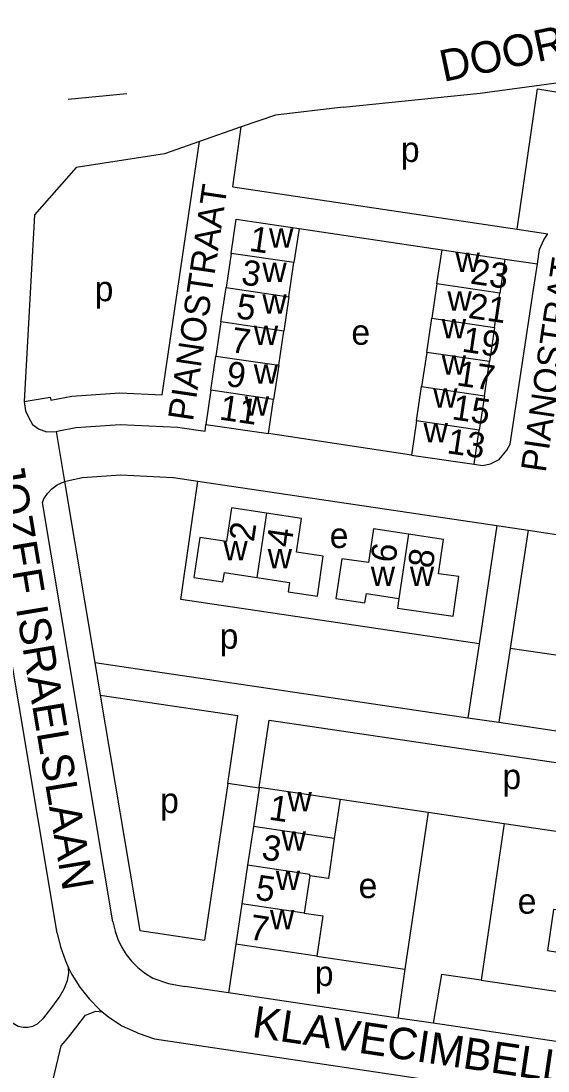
# Model space of a CAD drawing. Extents: x 163012 to 165277, y 382513 to 383987.
# Drawn here: x 164286.1 to 164369.8, y 383209.4 to 383376 of the extents above; entities that cross this region are included whole.
import ezdxf

# ---------------------------------------------------------------- set-up
doc = ezdxf.new("R2010")
doc.units = 0
for name, color, linetype in [('BLT_Basislijn', 7, 'Continuous'), ('BLT_Bebouwing', 7, 'Continuous'), ('BLT_Centroide', 7, 'Continuous'), ('BLT_Huisnummer', 7, 'Continuous'), ('BLT_Huisnummer_ tussenligend', 7, 'Continuous'), ('BLT_Onderverdeling_panden', 7, 'Continuous'), ('BLT_Straatnaam', 7, 'Continuous'), ('BLT_Straatnaam_verkleind', 7, 'Continuous'), ('BLT_Vlakafsluiter', 7, 'Continuous')]:
    doc.layers.add(name, color=color, linetype=linetype)

msp = doc.modelspace()

# ---------------------------------------------------------------- linework, layer by layer
at = {"layer": 'BLT_Basislijn'}
for p, q in [((164293.6, 383363.66), (164302.9, 383364.52)), ((164308.49, 383316.69), (164314.42, 383356.92)), ((164330.23, 383343.11), (164352.93, 383339.75)), ((164364.88, 383343.03), (164369.75, 383342.26)), ((164362.89, 383338.26), (164368.07, 383337.49)), ((164348.07, 383307.16), (164325.39, 383310.55)), ((164310.28, 383303.58), (164314.17, 383303)), ((164314.17, 383303), (164361.65, 383295.96)), ((164361.65, 383295.96), (164358.8, 383277.21)), ((164361.65, 383295.96), (164366.6, 383295.22)), ((164366.6, 383295.22), (164363.74, 383276.47)), ((164366.6, 383295.22), (164417.23, 383287.72)), ((164358.8, 383277.21), (164357.01, 383265.47)), ((164363.74, 383276.47), (164361.96, 383264.74)), ((164412.77, 383269.34), (164363.74, 383276.47)), ((164297.82, 383274.22), (164357.01, 383265.47)), ((164298.69, 383269.03), (164320.53, 383265.81)), ((164318.94, 383255.03), (164320.53, 383265.81)), ((164323.91, 383254.47), (164325.48, 383265.08)), ((164325.48, 383265.08), (164404.1, 383253.46)), ((164357.01, 383265.47), (164361.96, 383264.74)), ((164361.96, 383264.74), (164408.23, 383257.91)), ((164336.74, 383252.56), (164350.72, 383250.49)), ((164350.72, 383250.49), (164347.05, 383225.58)), ((164350.72, 383250.49), (164362.81, 383248.7)), ((164362.81, 383248.7), (164372.46, 383247.27)), ((164320.21, 383229.55), (164319.06, 383221.78)), ((164333.07, 383227.65), (164347.05, 383225.58)), ((164347.05, 383225.58), (164345.9, 383217.81)), ((164319.06, 383221.78), (164312.08, 383222.81)), ((164359.13, 383223.8), (164371.75, 383221.94)), ((164345.9, 383217.81), (164319.06, 383221.78)), ((164351.55, 383216.97), (164345.9, 383217.81)), ((164388.55, 383211.49), (164351.55, 383216.97)), ((164307.28, 383214.49), (164391.56, 383201.97))]:
    msp.add_line(p, q, dxfattribs=at)
for points in [[(164337.22, 383362.36), (164358.98, 383364.61), (164370.66, 383366.16), (164374.93, 383366.82), (164382.02, 383368.3)], [(164364.88, 383343.03), (164368.06, 383365.25), (164381.21, 383363.14)], [(164337.22, 383362.36), (164326.5, 383361.12), (164321.06, 383359.23)], [(164321.06, 383359.23), (164314.42, 383356.92)], [(164319.7, 383349.73), (164321.06, 383359.23)], [(164314.42, 383356.92), (164308.85, 383354.98), (164294.84, 383352.77), (164288.23, 383345.29), (164286.6, 383315.63)], [(164319.7, 383349.73), (164364.88, 383343.03)], [(164368.07, 383337.49), (164368.42, 383339.78), (164369.09, 383341.3), (164369.75, 383342.26)], [(164358.04, 383305.7), (164359.34, 383305.52), (164360.63, 383305.74), (164361.99, 383306.47), (164363.24, 383307.91), (164363.76, 383308.86), (164367.46, 383333.41), (164368.07, 383337.49)], [(164286.6, 383315.63), (164290.72, 383316.33), (164290.81, 383315.84)], [(164290.81, 383315.84), (164294.17, 383316.5), (164301.79, 383317.03), (164308.49, 383316.69)], [(164286.6, 383315.63), (164286.81, 383314.19), (164287.3, 383313.17), (164287.93, 383312.03), (164288.86, 383311.31), (164290.14, 383310.84), (164291.66, 383310.88)], [(164291.66, 383310.88), (164292.09, 383311), (164294.82, 383311.53), (164301.84, 383312.02), (164310.96, 383311.56), (164315.34, 383310.92), (164315.42, 383312.01)], [(164291.86, 383231.28), (164279.61, 383304.09)], [(164300.69, 383233.05), (164289.49, 383299.61), (164289.73, 383300.21), (164290.28, 383301.03), (164290.99, 383301.77), (164291.86, 383302.43), (164292.98, 383302.96)], [(164292.98, 383302.96), (164293.88, 383303.19), (164295.88, 383303.59), (164301.92, 383304), (164310.18, 383303.59), (164310.28, 383303.58)], [(164292.98, 383302.96), (164297.82, 383274.22)], [(164358.8, 383277.21), (164311.46, 383284.25), (164314.17, 383303)], [(164297.82, 383274.22), (164298.69, 383269.03)], [(164298.69, 383269.03), (164304.97, 383231.7)], [(164318.94, 383255.03), (164315.25, 383230.16)], [(164323.88, 383254.27), (164318.94, 383255.03)], [(164362.81, 383248.7), (164359.13, 383223.8)], [(164300.69, 383233.05), (164301.03, 383231.6), (164301.48, 383230.32), (164302.07, 383229.08), (164302.8, 383227.9), (164303.66, 383226.82), (164304.62, 383225.84), (164305.68, 383224.98), (164307, 383224.12), (164309.5, 383223.28), (164312.08, 383222.81)], [(164291.86, 383231.28), (164292.37, 383229.09), (164293.14, 383226.88), (164293.66, 383225.79)], [(164304.97, 383231.7), (164315.25, 383230.16)], [(164272.17, 383224.65), (164275.63, 383223.09), (164280.5, 383220.6), (164283.15, 383218.41), (164283.9, 383217.7), (164284.86, 383216.97), (164285.65, 383216.54), (164286.42, 383216.37), (164287.16, 383216.37), (164287.95, 383216.53), (164288.74, 383216.9), (164289.7, 383217.85), (164290.82, 383219.29), (164292.14, 383221.04), (164292.96, 383222.46), (164293.46, 383223.78), (164293.68, 383224.91), (164293.66, 383225.79)], [(164293.66, 383225.79), (164294.17, 383224.74), (164295.43, 383222.72), (164296.9, 383220.85), (164298.56, 383219.17), (164298.99, 383218.81)], [(164359.13, 383223.8), (164352.83, 383224.73), (164351.55, 383216.97)], [(164292.48, 383213.42), (164293.45, 383214.52), (164294.79, 383216.25), (164296.31, 383218.27), (164297.96, 383218.88), (164298.99, 383218.81)], [(164298.99, 383218.81), (164299.98, 383217.99)], [(164299.98, 383217.99), (164302.1, 383216.57), (164304.26, 383215.6)], [(164304.26, 383215.6), (164304.71, 383215.41), (164307.28, 383214.49)], [(164269.92, 383176.86), (164270.61, 383178.43), (164275.99, 383182.3), (164282.49, 383187.94), (164285.5, 383191.75), (164287.9, 383196.02), (164289.7, 383201.81), (164292.48, 383213.42)]]:
    msp.add_lwpolyline(points, dxfattribs=at)
at = {"layer": 'BLT_Bebouwing'}
for p, q in [((164319.46, 383339.16), (164320.27, 383344.59)), ((164320.27, 383344.59), (164330.23, 383343.11)), ((164330.23, 383343.11), (164329.43, 383337.69)), ((164352.12, 383334.31), (164352.93, 383339.75)), ((164352.93, 383339.75), (164362.89, 383338.26)), ((164319.46, 383339.16), (164318.65, 383333.73)), ((164362.89, 383338.26), (164362.08, 383332.84)), ((164328.62, 383332.26), (164329.43, 383337.69)), ((164317.84, 383328.3), (164318.65, 383333.73)), ((164352.12, 383334.31), (164351.31, 383328.88)), ((164361.27, 383327.41), (164362.08, 383332.84)), ((164328.62, 383332.26), (164327.81, 383326.83)), ((164317.84, 383328.3), (164317.04, 383322.87)), ((164350.5, 383323.45), (164351.31, 383328.88)), ((164327, 383321.4), (164327.81, 383326.83)), ((164361.27, 383327.41), (164360.46, 383321.98)), ((164316.23, 383317.44), (164317.04, 383322.87)), ((164350.5, 383323.45), (164349.69, 383318.02)), ((164327, 383321.4), (164326.19, 383315.97)), ((164359.66, 383316.55), (164360.46, 383321.98)), ((164348.88, 383312.59), (164349.69, 383318.02)), ((164316.23, 383317.44), (164315.42, 383312.01)), ((164359.66, 383316.55), (164358.85, 383311.12)), ((164325.39, 383310.55), (164326.19, 383315.97)), ((164315.42, 383312.01), (164325.39, 383310.55)), ((164348.88, 383312.59), (164348.07, 383307.16)), ((164358.04, 383305.7), (164358.85, 383311.12)), ((164348.07, 383307.16), (164358.04, 383305.7)), ((164323.88, 383254.27), (164323.91, 383254.47)), ((164323.91, 383254.47), (164336.74, 383252.56)), ((164323.88, 383254.27), (164322.98, 383248.18)), ((164336.74, 383252.56), (164335.82, 383246.28)), ((164322.98, 383248.18), (164322.07, 383242.05)), ((164322.07, 383242.05), (164321.16, 383235.92)), ((164331.94, 383240.38), (164331.06, 383234.45)), ((164321.16, 383235.92), (164320.21, 383229.55)), ((164333.07, 383227.65), (164320.21, 383229.55))]:
    msp.add_line(p, q, dxfattribs=at)
for points in [[(164325.06, 383297.94), (164319.51, 383298.77), (164318.71, 383293.42), (164314.46, 383294.05), (164313.52, 383287.73), (164318.16, 383287.04), (164318.38, 383288.52), (164323.53, 383287.72)], [(164323.53, 383287.72), (164328.71, 383286.92), (164328.5, 383285.43), (164333.14, 383284.76), (164334.06, 383291.13), (164329.85, 383291.74), (164330.61, 383297.11), (164325.06, 383297.94)], [(164347.6, 383294.6), (164342.04, 383295.43), (164341.24, 383290.08), (164337, 383290.71), (164336.06, 383284.39), (164340.7, 383283.7), (164340.92, 383285.18), (164346.08, 383284.38)], [(164346.08, 383284.38), (164345.85, 383282.84), (164354.7, 383281.56), (164355.61, 383287.86), (164352.36, 383288.32), (164353.16, 383293.77), (164347.6, 383294.6)], [(164335.82, 383246.28), (164334.9, 383239.95), (164331.94, 383240.38)], [(164331.06, 383234.45), (164334.01, 383234.02), (164333.07, 383227.65)], [(164373.62, 383234.59), (164370.65, 383235.02), (164369.69, 383228.5), (164372.65, 383228.06)]]:
    msp.add_lwpolyline(points, dxfattribs=at)
at = {"layer": 'BLT_Onderverdeling_panden'}
for p, q in [((164329.43, 383337.69), (164319.46, 383339.16)), ((164318.65, 383333.73), (164328.62, 383332.26)), ((164362.08, 383332.84), (164352.12, 383334.31)), ((164327.81, 383326.83), (164317.84, 383328.3)), ((164351.31, 383328.88), (164361.27, 383327.41)), ((164317.04, 383322.87), (164327, 383321.4)), ((164360.46, 383321.98), (164350.5, 383323.45)), ((164349.69, 383318.02), (164359.66, 383316.55)), ((164326.19, 383315.97), (164316.23, 383317.44)), ((164358.85, 383311.12), (164348.88, 383312.59)), ((164325.06, 383297.94), (164323.53, 383287.72)), ((164347.6, 383294.6), (164346.08, 383284.38)), ((164335.82, 383246.28), (164322.98, 383248.18)), ((164331.06, 383234.45), (164321.16, 383235.92))]:
    msp.add_line(p, q, dxfattribs=at)
msp.add_lwpolyline([(164331.94, 383240.38), (164331.97, 383240.58), (164322.07, 383242.05)], dxfattribs=at)
at = {"layer": 'BLT_Vlakafsluiter'}
msp.add_line((164291.66, 383310.88), (164292.98, 383302.96), dxfattribs=at)

# ---------------------------------------------------------------- texts
at = {"layer": 'BLT_Centroide'}
for s, p in [('p', (164346.4, 383353.67)), ('w', (164325.47, 383340.05)), ('w', (164355.07, 383336.19)), ('w', (164324.41, 383334.6)), ('p', (164297.79, 383331.57)), ('w', (164353.79, 383330.05)), ('w', (164324.41, 383329.6)), ('e', (164338.54, 383324.66)), ('w', (164352.88, 383325.66)), ('w', (164323.05, 383324.6)), ('w', (164352.88, 383319.91)), ('w', (164323.05, 383318.47)), ('w', (164351.52, 383314.68)), ('w', (164321.61, 383313.39)), ('w', (164350, 383309.15)), ('e', (164335.1, 383292.41)), ('w', (164318.22, 383290.43)), ('w', (164325.26, 383289.19)), ('w', (164341.62, 383286.39)), ('w', (164347.83, 383286.39)), ('p', (164317.63, 383276.41)), ('p', (164362.52, 383254.14)), ('p', (164308.19, 383250.35)), ('w', (164328.4, 383250.6)), ('w', (164327.47, 383244.38)), ('w', (164326.54, 383238.13)), ('e', (164339.69, 383236.83)), ('e', (164364.94, 383234.36)), ('w', (164325.62, 383231.88)), ('p', (164332.74, 383222.9))]:
    msp.add_text(s, height=4, dxfattribs=at).set_placement(p)
at = {"layer": 'BLT_Huisnummer'}
for s, rotation, p in [('1', 351.5821, (164322.19, 383339.58)), ('23', 351.5821, (164357.28, 383334.39)), ('5', 351.5821, (164320.11, 383328.9)), ('17', 351.5821, (164355.11, 383318.23)), ('11', 351.5821, (164317.45, 383312.81)), ('13', 351.5821, (164353.57, 383307.47)), ('2', 81.5821, (164323.05, 383293.27)), ('4', 81.5821, (164328.98, 383292.37)), ('6', 81.5821, (164345.5, 383289.92)), ('8', 81.5821, (164351.44, 383289.05)), ('1', 351.5813, (164325.3, 383249.32)), ('7', 351.581, (164322.2, 383230.32))]:
    msp.add_text(s, height=4, rotation=rotation, dxfattribs=at).set_placement(p)
at = {"layer": 'BLT_Huisnummer_ tussenligend'}
for s, rotation, p in [('3', 351.5821, (164320.91, 383334.27)), ('21', 351.5821, (164356.96, 383328.94)), ('7', 351.5821, (164319.25, 383323.53)), ('19', 351.5821, (164355.96, 383323.6)), ('9', 351.5821, (164318.51, 383318.15)), ('15', 351.5821, (164354.36, 383312.85)), ('3', 351.5813, (164324.15, 383243.02)), ('5', 351.5813, (164323.17, 383236.63))]:
    msp.add_text(s, height=4, rotation=rotation, dxfattribs=at).set_placement(p)
at = {"layer": 'BLT_Straatnaam'}
for s, rotation, p in [('DOORNAKKERSWEG', 11.924, (164353.16, 383366.36)), ('JOZEF ISRAELSLAAN', 279.4601, (164281.49, 383305.6)), ('KLAVECIMBELLAAN', 351.5769, (164322.62, 383214.82))]:
    msp.add_text(s, height=5, rotation=rotation, dxfattribs=at).set_placement(p)
at = {"layer": 'BLT_Straatnaam_verkleind'}
for s, p in [('PIANOSTRAAT', (164313.37, 383312.41)), ('PIANOSTRAT', (164369.38, 383304.28))]:
    msp.add_text(s, height=4, rotation=81.5928, dxfattribs=at).set_placement(p)

doc.saveas('drawing.dxf')
